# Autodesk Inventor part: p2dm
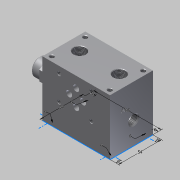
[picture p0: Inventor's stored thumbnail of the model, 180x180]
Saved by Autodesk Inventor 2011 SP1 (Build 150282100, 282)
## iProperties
Created: 2010-08
Part Number: p2dm
Document SubType Name: Листовой металл
Designer: sazanov
Density: 1 g/cm^3
Sheet Metal Rule: По умолчанию
Mass: 294.147 g
Surface Area: 427.434 cm^2
Volume: 294.147 cm^3
Author: sazanov
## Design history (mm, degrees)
sketch "Эскиз1"
  geometry: L1 (0, 0)-(0, 54); L2 (0, 54)-(85, 54); L3 (85, 54)-(85, 0); L4 (85, 0)-(0, 0); L5 (79, 58.327)-(79, -6.618); L6 (6, 58.327)-(6, -10.737); L7 (-7.523, 48)-(92.846, 48); L8 (-8.896, 6)-(90.649, 6); C1 r 3 at (79, 48); C2 r 3 at (6, 48); C3 r 3 at (6, 6); C4 r 3 at (79, 6)
  constraints: 16 end point, 8 point on line, 5 parallel, 4 centre point, 1 perpendicular
  dimensions: "d0" = 54 distance of L1.start L1.end; "d1" = 85 distance of L1.end L2.end; "d2" = 54 distance of L2.end L3.end; "d22" = 6 horizontal distance of L1.end L6.start; "d23" = 6 horizontal distance of L2.end L5.start; "d24" = 6 vertical distance of L3.end L8.end; "d25" = 6 vertical distance of L7.end L2.end; "d26" = 6 diameter of C1; "d27" = 6 diameter of C2; "d28" = 6 diameter of C3; "d29" = 6 diameter of C4
extrude "Выдавливание5" new body sketch "Эскиз1" distance "d40" = 70; taper "d41" = 0 deg
sketch "Эскиз5"
  geometry: L1 (85, 0)-(85, -70) reference; L2 (0, 0)-(85, 0) reference; 1 further point
  dimensions: "d56" = 47 distance from line of L2 point (59, -47); "d57" = 26 distance from line of point (59, -47) L1
hole "Отверстие1" sketch "Эскиз5" at (59, -47) diameter "d58" = 14.95; stored, may be unused: countersink angle "d62" = 90 deg, drill point angle "d64" = 118 deg; dims "d59" = 6, "d60" = 18, "d61" = 2, "d63" = 15
sketch "Эскиз6"
  geometry: L1 (0, 0)-(85, 0) reference; C1 r 9 at (59, -47) reference; 1 further point
  dimensions: "d65" = 33 distance of point (26, -47) C1.centre; "d66" = 47 distance from line of L1 point (26, -47)
hole "Отверстие2" sketch "Эскиз6" at (26, -47) diameter "d67" = 14.95; stored, may be unused: countersink angle "d71" = 90 deg, drill point angle "d73" = 118 deg; dims "d68" = 6, "d69" = 18, "d70" = 2, "d72" = 15
sketch "Эскиз7"
  geometry: L1 (0, 0)-(0, 54) reference; L2 (0, 54)-(-85, 54) reference; 1 further point
  dimensions: "d74" = 17.5 distance from line of point (-17.5, 29.5) L1; "d75" = 24.5 distance from line of point (-17.5, 29.5) L2
hole "Отверстие3" sketch "Эскиз7" at (-17.5, 29.5) diameter "d76" = 18.631; stored, may be unused: countersink angle "d80" = 90 deg, drill point angle "d82" = 118 deg; dims "d77" = 32, "d78" = 20, "d79" = 2, "d81" = 35
sketch "Эскиз8"
  geometry: L1 (0, 54)-(-85, 54) reference; L2 (-85, 54)-(-85, 0) reference; 1 further point
  dimensions: "d83" = 24.5 distance from line of L1 point (-67.5, 29.5); "d84" = 17.5 distance from line of point (-67.5, 29.5) L2
hole "Отверстие4" sketch "Эскиз8" at (-67.5, 29.5) diameter "d85" = 14.95; stored, may be unused: countersink angle "d89" = 90 deg, drill point angle "d91" = 118 deg; dims "d86" = 32, "d87" = 16, "d88" = 2, "d90" = 35
sketch "Эскиз9"
  geometry: L1 (0, 0)-(0, 54) reference; L2 (0, 54)-(85, 54) reference; 1 further point
  dimensions: "d100" = 17.5 distance from line of point (17.5, 29.5) L1; "d101" = 24.5 distance from line of L2 point (17.5, 29.5)
hole "Отверстие5" sketch "Эскиз9" at (17.5, 29.5) diameter "d92" = 14.95; stored, may be unused: countersink angle "d96" = 90 deg, drill point angle "d98" = 118 deg; dims "d93" = 32, "d94" = 16, "d95" = 2, "d97" = 35
sketch "Эскиз10"
  geometry: L1 (0, 54)-(85, 54) reference; L2 (85, 54)-(85, 0) reference; 1 further point
  dimensions: "d102" = 24.5 distance from line of point (67.5, 29.5) L1; "d103" = 17.5 distance from line of L2 point (67.5, 29.5)
hole "Отверстие6" sketch "Эскиз10" at (67.5, 29.5) diameter "d104" = 14.95; stored, may be unused: countersink angle "d108" = 90 deg, drill point angle "d110" = 118 deg; dims "d105" = 15, "d106" = 16, "d107" = 2, "d109" = 34
sketch "Эскиз11"
  geometry: L1 (85, 70)-(0, 70) reference; L2 (0, 0)-(0, 70) reference; 1 further point
  dimensions: "d111" = 21 distance from line of point (21, 61.5) L2; "d112" = 8.5 distance from line of point (21, 61.5) L1
hole "Отверстие7" sketch "Эскиз11" at (21, 61.5) diameter "d113" = 4.134; stored, may be unused: countersink angle "d117" = 90 deg, drill point angle "d119" = 118 deg; dims "d114" = 12, "d115" = 5, "d116" = 2, "d118" = 15
sketch "Эскиз12"
  geometry: C1 r 2.5 at (21, 61.5) reference; 1 further point
  dimensions: "d123" = 0.75 vertical distance of point (61.5, 62.25) C1.centre; "d153" = 40.5 horizontal distance of point (61.5, 62.25) C1.centre
pattern_linear "Прямоуг.массив1" dims "d122" = 31
hole "Отверстие8" sketch "Эскиз12" diameter "d124" = 4.134; stored, may be unused: countersink angle "d128" = 90 deg, drill point angle "d130" = 118 deg; dims "d125" = 12, "d126" = 5, "d127" = 2, "d129" = 15
sketch "Эскиз13"
  geometry: C1 r 2.5 at (61.5, 62.25) reference; C2 r 2.5 at (21, 61.5) reference; 1 further point
  dimensions: "d132" = 32.5 distance of point (61.5, 29.75) C1.centre; "d133" = 31.75 vertical distance of point (61.5, 29.75) C2.centre
hole "Отверстие9" sketch "Эскиз13" at (61.5, 29.75) diameter "d134" = 4.134; stored, may be unused: countersink angle "d138" = 90 deg, drill point angle "d140" = 118 deg; dims "d135" = 12, "d136" = 5, "d137" = 2, "d139" = 15
sketch "Эскиз14"
  geometry: C1 r 2.5 at (21, 61.5) reference; 1 further point
  dimensions: "d141" = 5.1 vertical distance of point (42.5, 56.4) C1.centre; "d142" = 21.5 horizontal distance of point (42.5, 56.4) C1.centre
hole "Отверстие10" sketch "Эскиз14" at (42.5, 56.4) diameter "d143" = 7.5; stored, may be unused: countersink angle "d147" = 90 deg, drill point angle "d149" = 118 deg; dims "d144" = 12, "d145" = 5, "d146" = 2, "d148" = 10
pattern_linear "Прямоуг.массив2" dims "d152" = 20.8
sketch "Эскиз15"
  geometry: C1 r 2.5 at (21, 61.5) reference; 1 further point
  dimensions: "d154" = 12.7 horizontal distance of point (33.7, 46) C1.centre; "d155" = 15.5 vertical distance of point (33.7, 46) C1.centre
hole "Отверстие11" sketch "Эскиз15" at (33.7, 46) diameter "d156" = 7.5; stored, may be unused: countersink angle "d160" = 90 deg, drill point angle "d162" = 118 deg; dims "d157" = 12, "d158" = 5, "d159" = 2, "d161" = 10
pattern_linear "Прямоуг.массив3" dims "d165" = 17.5
sketch "Эскиз16"
  geometry: L1 (0, 0)-(0, 54) reference; L2 (0, 0)-(70, 0) reference; C1 r 11 at (28, 30); 1 further point
  constraints: 1 centre point, 1 coincident
  dimensions: "d166" = 28 distance from line of L1 point (28, 30); "d168" = 30 distance from line of L2 point (28, 30); "d169" = 22 diameter of C1
extrude "Выдавливание10" join sketch "Эскиз16" distance "d170" = 11; taper "d171" = 0 deg
sketch "Эскиз17"
  geometry: L1 (6.351, 11)-(12.702, 0); L2 (12.702, 0)-(6.351, -11); L3 (6.351, -11)-(-6.351, -11); L4 (-6.351, -11)-(-12.702, 0); L5 (-12.702, 0)-(-6.351, 11); L6 (-6.351, 11)-(6.351, 11); C1 r 11 at (0, 0) reference; 2 further points
  constraints: 12 end point, 1 coincident, 1 horizontal, 13 other
  dimensions: "d172" = 22 distance between parallel lines of L4 L1
extrude "Выдавливание11" join sketch "Эскиз17" distance "d173" = 12; taper "d174" = 0 deg
sketch "Эскиз18"
  geometry: C1 r 11 at (0, 0); 1 further point
  constraints: 1 centre point
  dimensions: "d175" = 22 diameter of C1
extrude "Выдавливание12" join sketch "Эскиз18" distance "d176" = 11; taper "d177" = 0 deg
chamfer "Фаска1" distance "d178" = 2; stored, may be unused: second distance "d179" = 2, angle "d180" = 45 deg
sketch "Эскиз19"
  geometry: C1 r 9 at (0, 0) reference; 2 further points
  constraints: 1 coincident
hole "Отверстие12" sketch "Эскиз19" at (0, 0) diameter "d181" = 4.917; stored, may be unused: countersink angle "d185" = 90 deg, drill point angle "d187" = 118 deg; dims "d182" = 8, "d183" = 6, "d184" = 2, "d186" = 10
sketch "Эскиз20"
  geometry: L1 (0, 0)-(-70, 0) reference; L2 (0, 54)-(0, 0) reference; 1 further point
  dimensions: "d188" = 30 distance from line of point (-28, 30) L1; "d189" = 28 distance from line of point (-28, 30) L2
hole "Отверстие13" sketch "Эскиз20" at (-28, 30) diameter "d190" = 11.445; stored, may be unused: countersink angle "d194" = 90 deg, drill point angle "d196" = 118 deg; dims "d191" = 8, "d192" = 14, "d193" = 2, "d195" = 10
sketch "Эскиз21"
  geometry: L1 (59.913, -63.424)-(55.555, -63.424); L2 (55.555, -63.424)-(55.555, -57.867); L3 (55.555, -57.867)-(59.913, -57.867); L4 (59.913, -57.867)-(59.913, -63.424); L5 (28.308, -57.689)-(28.308, -63.246); L6 (28.308, -63.246)-(23.95, -63.246); L7 (23.95, -63.246)-(23.95, -57.689); L8 (23.95, -57.689)-(28.308, -57.689); L9 (12.342, -3.191)-(12.342, -8.748); L10 (12.342, -8.748)-(7.984, -8.748); L11 (7.984, -8.748)-(7.984, -3.191); L12 (7.984, -3.191)-(12.342, -3.191); L13 (75.062, -4.202)-(75.062, -9.759); L14 (75.062, -9.759)-(70.703, -9.759); L15 (70.703, -9.759)-(70.703, -4.202); L16 (70.703, -4.202)-(75.062, -4.202)
  constraints: 8 other
feature "Рельеф1" sketch "Эскиз21" dims "d107" = 2, "d197" = 1, "d198" = 0
sketch "Эскиз22"
  geometry: L1 (-48.122, 13.703)-(-48.122, 20.427); L2 (-48.122, 20.427)-(-42.266, 20.427); L3 (-42.266, 20.427)-(-42.266, 13.703); L4 (-42.266, 13.703)-(-48.122, 13.703)
  constraints: 2 other
feature "Рельеф2" sketch "Эскиз22" dims "d107" = 2, "d199" = 1, "d200" = 0
sketch "Эскиз23"
  geometry: L1 (0, 54)-(85, 54) reference; L2 (0, 0)-(0, 54) reference; 1 further point
  dimensions: "d201" = 6 distance from line of point (6, 48) L2; "d202" = 6 distance from line of point (6, 48) L1
hole "Отверстие14" sketch "Эскиз23" at (6, 48) diameter "d203" = 4.917; stored, may be unused: countersink angle "d207" = 90 deg, drill point angle "d209" = 118 deg; dims "d204" = 13, "d205" = 6, "d206" = 2, "d208" = 15
pattern_linear "Прямоуг.массив4" dims "d212" = 73, "d215" = 42
hole "Отверстие15" sketch "Эскиз1" diameter "d216" = 4.917; stored, may be unused: countersink angle "d220" = 90 deg, drill point angle "d222" = 118 deg; dims "d217" = 13, "d218" = 6, "d219" = 2, "d221" = 15
node "Твердое тело2"
other parameters: "Толщина" = 0.5, "Поправка" = 4.4, "Радиус_гибки" = 0.5 (= Толщина), "Ширина_просечки" = 0.5 (= Толщина), "Глубина_просечки" = 0.25 (= 0.5 x Толщина), "Размер_просечки" = 2 (= 4 x Толщина), "Зазор_стыка" = 0.01, "Мин_остаток" = 1 (= 2 x Толщина), "Радиус_перехода" = 0.5 (= Радиус_гибки), "Радиус_Якоби" = 0.5 (= Толщина), "Размер_зазора" = 0.5 (= Толщина)
